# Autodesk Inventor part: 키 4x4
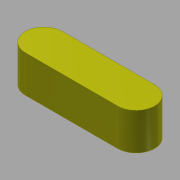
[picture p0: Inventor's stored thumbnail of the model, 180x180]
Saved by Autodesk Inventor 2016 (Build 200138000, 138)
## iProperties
Created: 2014-10
Part Number: 키 4x4
Document SubType Name: Modeling
Designer: KYOUNG IL JANG
Density: 7.86 g/cm^3
Mass: 1.65269 g
Surface Area: 2.35398 cm^2
Volume: 0.210265 cm^3
Material: 강철, 연강
Appearance: 노란색
Author: SeoGD™ [www.esajin.kr]
Revision Number: 1
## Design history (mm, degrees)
sketch "스케치1"
  geometry: L1 (-5, -2)-(5, -2); L2 (5, 2)-(-5, 2); A1 r 2 centre (5, 0) between (5, -2) and (5, 2); A2 r 2 centre (-5, 0) between (-5, 2) and (-5, -2); 2 further points
  constraints: 4 end point, 4 point on circle, 4 tangent, 2 centre point, 1 horizontal, 1 horizontal alignment, 1 midpoint, 1 parallel, 1 vertical alignment
  dimensions: "d0" = 4 distance between parallel lines of L1 L2; "d1" = 14 dimension on A1 A2
extrude "돌출1" new body sketch "스케치1" stored distance "d2" = 4; taper "d3" = 0 deg
node "솔리드1"
